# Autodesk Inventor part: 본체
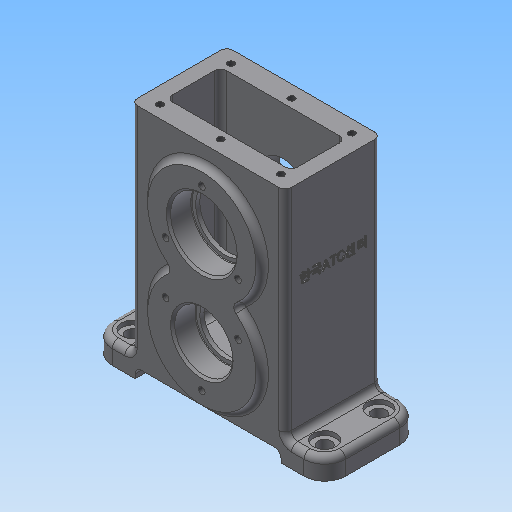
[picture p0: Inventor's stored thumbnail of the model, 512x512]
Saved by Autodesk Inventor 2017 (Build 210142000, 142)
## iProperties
Created: 2020-03
Part Number: 본체
Material: 일반
Document SubType Name: Modeling
Designer: mduedu
Density: 1 g/cm^3
Appearance: 기본값
Mass: 220.307 g
Surface Area: 576.062 cm^2
Volume: 220.307 cm^3
Author: mduedu
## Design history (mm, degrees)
sketch "스케치1"
  geometry: L1 (-56, 0)-(56, 0); L2 (56, 0)-(56, 10); L3 (-56, 10)-(-56, 0); L4 (37, 10)-(37, 114); L5 (37, 114)-(-37, 114); L6 (-37, 114)-(-37, 10); L7 (56, 10)-(37, 10); L8 (-37, 10)-(-56, 10); L9 (0, 0)-(0, 114); 1 further point
  constraints: 18 end point, 5 parallel, 2 midpoint, 2 vertical, 1 coincident, 1 horizontal, 1 perpendicular
  dimensions: "d0" = 112 distance of L1.start L1.end; "d2" = 10 distance of L1.end L2.end; "d3" = 114 distance between parallel lines of L5 L1; "d4" = 74 distance between parallel lines of L4 L6
extrude "돌출1" new body sketch "스케치1" stored distance "d5" = 46; taper "d6" = 0 deg
sketch "스케치2"
  geometry: L1 (56, 0)-(-56, 0) reference; C1 r 26 at (0, 34); C2 r 26 at (0, 79); 1 further point
  constraints: 2 centre point, 2 vertical alignment, 1 equal radius
  dimensions: "d7" = 52 diameter of C2; "d9" = 34 distance from line of C1.centre L1; "d10" = 45 distance of C2.centre C1.centre
extrude "돌출2" join sketch "스케치2" stored distance "d11" = 52; taper "d12" = 0 deg
fillet "모깎기1" dims "d13" = 3
fillet "모깎기2" dims "d14" = 3
fillet "모깎기3" dims "d15" = 10
fillet "모깎기4" dims "d16" = 3
fillet "모깎기5" dims "d17" = 3
sketch "스케치3"
  geometry: L1 (-30, 114)-(30, 114); L2 (30, 114)-(30, 13); L3 (30, 13)-(-30, 13); L4 (-30, 13)-(-30, 114); L5 (-34, 114)-(34, 114) reference; L6 (46, 0)-(-46, 0) reference; 2 further points
  constraints: 8 end point, 2 parallel, 1 collinear, 1 horizontal, 1 midpoint, 1 perpendicular, 1 vertical alignment
  dimensions: "d18" = 60 distance between parallel lines of L2 L4; "d20" = 13 distance between parallel lines of L3 L6
extrude "돌출3" cut sketch "스케치3" stored distance "d21" = 26; taper "d22" = 0 deg
fillet "모깎기6" dims "d23" = 3
fillet "모깎기7" dims "d24" = 3
sketch "스케치4"
  geometry: L1 (-35, 0)-(35, 0); L2 (35, 0)-(35, 5); L3 (35, 5)-(-35, 5); L4 (-35, 5)-(-35, 0); 2 further points
  constraints: 8 end point, 2 parallel, 1 coincident, 1 horizontal, 1 midpoint, 1 perpendicular
  dimensions: "d25" = 70 distance of L1.start L1.end; "d27" = 5 distance of L1.end L2.end
extrude "돌출4" cut sketch "스케치4" stored distance "d28" = 26; taper "d29" = 0 deg
fillet "모깎기8" dims "d30" = 3
sketch "스케치5"
  geometry: A1 r 10 centre (-86, 33) between (-86, 43) and (-96, 33) reference; A2 r 10 centre (-86, 7) between (-96, 7) and (-86, -3) reference; A3 r 10 centre (6, 7) between (6, -3) and (16, 7) reference; A4 r 10 centre (6, 33) between (16, 33) and (6, 43) reference; 5 further points
  constraints: 4 coincident
hole "구멍1" sketch "스케치5" at (-86, 33), (-86, 7), (6, 7), (6, 33) diameter "d31" = 6.6; stored, may be unused: countersink angle "d35" = 90 deg, drill point angle "d37" = 118 deg; dims "d32" = 6, "d33" = 11, "d34" = 2, "d36" = 8
sketch "스케치6"
  geometry: A1 r 26 centre (0, 34) between (-16.403, 54.172) and (16.403, 54.172) reference; A2 r 3 centre (18.296, 56.5) between (16.403, 58.828) and (16.403, 54.172) reference; A3 r 26 centre (0, 79) between (16.403, 58.828) and (-16.403, 58.828) reference; A4 r 3 centre (-18.296, 56.5) between (-16.403, 54.172) and (-16.403, 58.828) reference; 2 further points
  constraints: 1 coincident
hole "구멍2" sketch "스케치6" at (0, 79) diameter "d38" = 28; stored, may be unused: countersink angle "d42" = 90 deg, drill point angle "d44" = 118 deg; dims "d39" = 6, "d40" = 32, "d41" = 11, "d43" = 8
sketch "스케치7"
  geometry: C1 r 16 at (0, 79) reference; A1 r 26 centre (0, 34) between (-16.403, 54.172) and (16.403, 54.172) reference; A2 r 3 centre (18.296, 56.5) between (16.403, 58.828) and (16.403, 54.172) reference; A3 r 26 centre (0, 79) between (16.403, 58.828) and (-16.403, 58.828) reference; A4 r 3 centre (-18.296, 56.5) between (-16.403, 54.172) and (-16.403, 58.828) reference; 2 further points
  constraints: 1 coincident
hole "구멍3" sketch "스케치7" at (0, 34) diameter "d45" = 24; stored, may be unused: countersink angle "d49" = 90 deg, drill point angle "d51" = 118 deg; dims "d46" = 6, "d47" = 28, "d48" = 11, "d50" = 8
sketch "스케치8"
  geometry: C1 r 14 at (0, 34) reference; A1 r 26 centre (0, 34) between (-16.403, 54.172) and (16.403, 54.172) reference; A2 r 3 centre (18.296, 56.5) between (16.403, 58.828) and (16.403, 54.172) reference; A3 r 26 centre (0, 79) between (16.403, 58.828) and (-16.403, 58.828) reference; A4 r 3 centre (-18.296, 56.5) between (-16.403, 54.172) and (-16.403, 58.828) reference; 2 further points
  constraints: 1 coincident
hole "구멍4" sketch "스케치8" at (0, 79) diameter "d52" = 24; stored, may be unused: countersink angle "d56" = 90 deg, drill point angle "d58" = 118 deg; dims "d53" = 6, "d54" = 28, "d55" = 11, "d57" = 8
sketch "스케치9" dims "d59" = 40
  geometry: C1 r 14 at (0, 34) reference; C2 r 16 at (0, 79) reference; A1 r 26 centre (0, 34) between (-16.403, 54.172) and (16.403, 54.172) reference; A2 r 3 centre (18.296, 56.5) between (16.403, 58.828) and (16.403, 54.172) reference; A3 r 26 centre (0, 79) between (16.403, 58.828) and (-16.403, 58.828) reference; A4 r 3 centre (-18.296, 56.5) between (-16.403, 54.172) and (-16.403, 58.828) reference; 3 further points
  constraints: 2 vertical alignment, 1 coincident, 2 other
hole "구멍5" sketch "스케치9" at (0, 99) diameter "d61" = 3.242; stored, may be unused: countersink angle "d65" = 90 deg, drill point angle "d67" = 118 deg; dims "d62" = 8, "d63" = 28, "d64" = 11, "d66" = 10
sketch "스케치10" dims "d71" = 40
  geometry: C1 r 1.621 at (17.321, 69) reference; C2 r 1.621 at (-17.321, 69) reference; C3 r 1.621 at (0, 99) reference; C4 r 14 at (0, 34) reference; C5 r 16 at (0, 79) reference; A1 r 26 centre (0, 34) between (-16.403, 54.172) and (16.403, 54.172) reference; A2 r 3 centre (18.296, 56.5) between (16.403, 58.828) and (16.403, 54.172) reference; A3 r 26 centre (0, 79) between (16.403, 58.828) and (-16.403, 58.828) reference; A4 r 3 centre (-18.296, 56.5) between (-16.403, 54.172) and (-16.403, 58.828) reference; 3 further points
  constraints: 2 vertical alignment, 1 coincident, 2 other
hole "구멍6" sketch "스케치10" at (0, 14) diameter "d72" = 3.242; stored, may be unused: countersink angle "d76" = 90 deg, drill point angle "d78" = 118 deg; dims "d73" = 8, "d74" = 28, "d75" = 11, "d77" = 10
sketch "스케치11"
  geometry: L1 (5, 6)-(63, 6); L2 (63, 6)-(63, 40); L3 (63, 40)-(5, 40); L4 (5, 40)-(5, 6); L5 (5, 6)-(63, 40); L6 (63, 6)-(5, 40); 7 further points
  constraints: 12 end point, 4 coincident, 4 midpoint, 2 parallel, 1 horizontal, 1 perpendicular
  dimensions: "d82" = 58 distance of L3.end L2.end; "d83" = 34 distance of L2.end L1.end
hole "구멍7" sketch "스케치11" at (5, 40), (63, 40), (63, 6), (5, 6), (34, 6), (34, 40) diameter "d84" = 3.242; stored, may be unused: countersink angle "d88" = 90 deg, drill point angle "d90" = 118 deg; dims "d85" = 8, "d86" = 28, "d87" = 11, "d89" = 10
fillet "모깎기9" dims "d91" = 0.3
chamfer "모따기1" distance "d92" = 1; stored, may be unused: second distance "d93" = 2, angle "d94" = 45 deg
sketch "스케치12"
  geometry: 2 further points
  constraints: 1 coincident
hole "구멍8" sketch "스케치12" at (0, -23) diameter "d95" = 4.917; stored, may be unused: countersink angle "d99" = 90 deg, drill point angle "d101" = 118 deg; dims "d96" = 8, "d97" = 12, "d98" = 1, "d100" = 10
sketch "스케치13"
  geometry: L1 (33, -13)-(7, -13) reference; L2 (40, 101)-(0, 101) reference; 3 further points
  constraints: 1 midpoint, 1 vertical alignment, 1 other
  dimensions: "d102" = 40 distance from line of point (20, 61) L2
feature "엠보싱1" sketch "스케치13" dims "d0" = 112, "d2" = 10, "d3" = 114, "d4" = 74, "d13" = 3, "d103" = 0.5, "d104" = 0
node "솔리드1"
mirror "대칭1"
pattern_circular "원형 패턴1" dims angle "d69" = 360 deg
pattern_circular "원형 패턴2" dims angle "d80" = 360 deg
mirror "대칭2"
node "투영된 루프1"
node "투영된 루프2"
node "투영된 루프3"
node "투영된 루프4"
node "투영된 루프5"
